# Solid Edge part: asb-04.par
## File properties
Author: nakano
Template: iso metric part.par
Last saved by: nakano
Revision: 4
Application: Solid Edge
Density: 2587.85314738901 kg/m^3
Accuracy: 0.990
Username: nakano
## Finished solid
Body 1: solid body, 49 faces, 122 edges, 56 vertices.
  Faces by surface: cylinder 25, plane 24
  Edges by curve: line 72, circle 50
Bounding box of the edges (mm): 57.150 x 24.206 x 34.722, from (-28.575, 0, -17.3609) to (28.575, 24.2062, 17.3609).
Cylindrical faces by radius (mm): R0.254 x3, R1.1938 x7, R1.5875 x2, R1.778 x3, R2.1844 x8, R4.0005 x2
Planar faces by outward normal: +x 4, +y 4, +z 5, -x 4, -y 1, -z 6
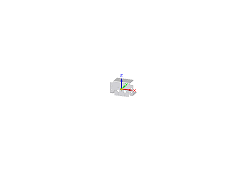
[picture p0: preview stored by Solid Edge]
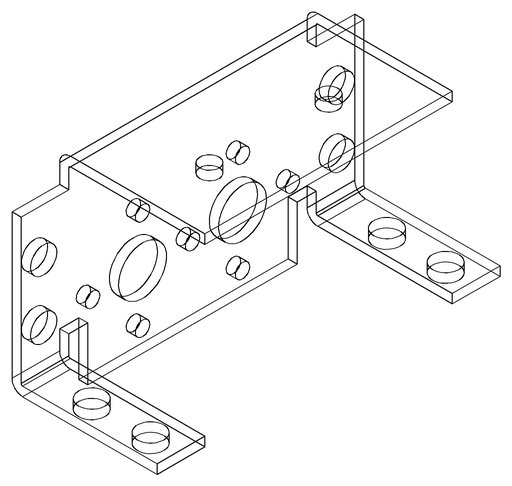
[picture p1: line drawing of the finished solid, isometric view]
